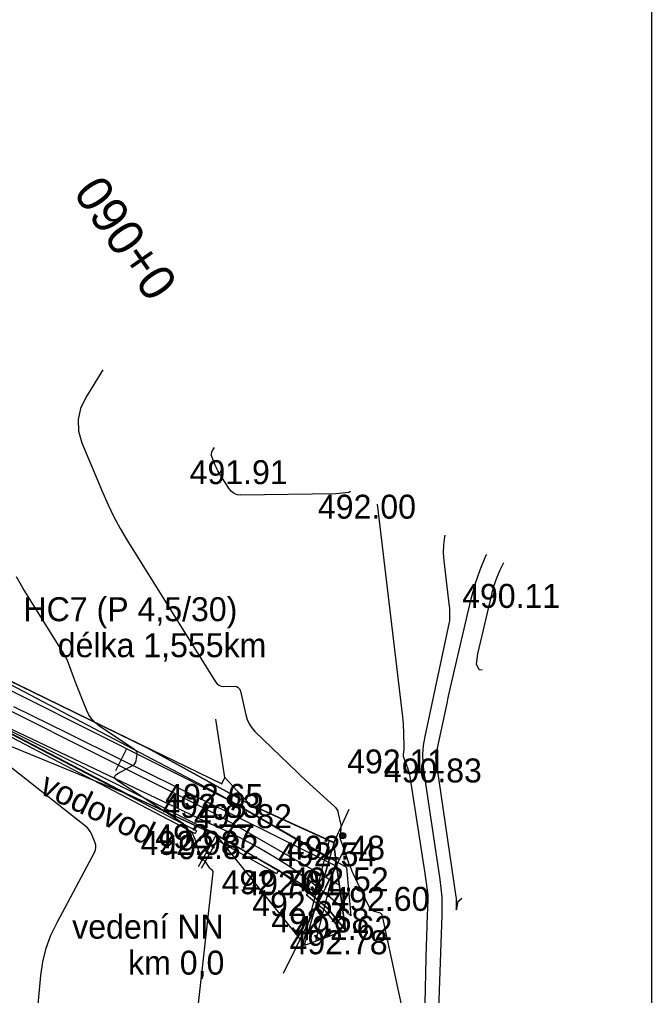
# Model space of a CAD drawing. Extents: x -636600 to -628587, y -1090963 to -1085869.
# Drawn here: x -629060 to -629007.3, y -1089333.5 to -1089252.1 of the extents above; entities that cross this region are included whole.
import ezdxf

# ---------------------------------------------------------------- set-up
doc = ezdxf.new("R2010")
doc.units = 0
for name, color, linetype in [('01_OBVOD PÚ', 7, 'Continuous'), ('01_PARCELY_NÁVRH_PC', 7, 'Continuous'), ('07_ELEKTRO', 7, 'Continuous'), ('07_OCH_P A POPISY TI', 7, 'Continuous'), ('07_VODOVOD', 7, 'Continuous'), ('08_LEGENDA_HV', 7, 'Continuous'), ('20', 7, 'Continuous'), ('23', 7, 'Continuous'), ('40', 7, 'Continuous'), ('52', 7, 'Continuous'), ('Ex_Major Contours', 7, 'Continuous'), ('Ex_Minor Contours', 7, 'Continuous'), ('HEKTOMETRY100', 7, 'Continuous'), ('HEKTOMETRY20', 7, 'Continuous'), ('HL_BODY', 7, 'Continuous'), ('koty_vše', 7, 'Continuous'), ('POLOMERY', 7, 'Continuous'), ('popis', 7, 'Continuous'), ('situace_osa', 7, 'Continuous'), ('situace_těleso', 7, 'Continuous'), ('situace_vozovka', 7, 'Continuous')]:
    doc.layers.add(name, color=color, linetype=linetype)

msp = doc.modelspace()

# ---------------------------------------------------------------- linework, layer by layer
at = {"layer": '01_OBVOD PÚ'}
msp.add_lwpolyline([(-629124.585, -1089274.487), (-629094.585, -1089282.287), (-629088.655, -1089283.337), (-629081.325, -1089299.317), (-629065.815, -1089310.587), (-629050.975, -1089316.657), (-629043.565, -1089320.077), (-629036.175, -1089329.257), (-629032.795, -1089328.017), (-629033.785, -1089320.707), (-629036.745, -1089319.347), (-629040.785, -1089317.497), (-629049.325, -1089312.807), (-629068.755, -1089303.327), (-629078.055, -1089290.717), (-629082.265, -1089284.067), (-629084.875, -1089279.947), (-629123.615, -1089269.707)], dxfattribs=at)
at = {"layer": '01_PARCELY_NÁVRH_PC'}
msp.add_lwpolyline([(-629124.585, -1089274.487), (-629123.615, -1089269.707), (-629084.875, -1089279.947), (-629078.055, -1089290.717), (-629068.755, -1089303.327), (-629049.325, -1089312.807), (-629040.785, -1089317.497), (-629036.745, -1089319.347), (-629033.785, -1089320.707), (-629032.795, -1089328.017), (-629034.275, -1089326.197), (-629035.865, -1089324.837), (-629038.385, -1089323.007), (-629043.565, -1089320.077), (-629050.975, -1089316.657), (-629073.783, -1089304.798), (-629074.736, -1089304.106), (-629074.865, -1089302.587), (-629088.655, -1089283.337), (-629094.585, -1089282.287)], close=True, dxfattribs=at)
at = {"layer": '07_ELEKTRO'}
msp.add_lwpolyline([(-629035.273, -1089328.926), (-629033.573, -1089322.277)], dxfattribs=at)
at = {"layer": '07_OCH_P A POPISY TI'}
msp.add_line((-629034.127, -1089322.051), (-629034.987, -1089325.019), dxfattribs=at)
for points in [[(-629034.127, -1089322.051), (-629042.702, -1089317.087), (-629070.938, -1089302.913), (-629075.743, -1089303.371)], [(-629034.987, -1089325.019), (-629044.128, -1089319.728), (-629071.513, -1089305.982), (-629072.074, -1089306.035)], [(-629034.15, -1089320.498), (-629036.363, -1089329.152)], [(-629034.15, -1089320.498), (-629033.725, -1089320.667), (-629036.225, -1089329.287), (-629036.363, -1089329.152)]]:
    msp.add_lwpolyline(points, dxfattribs=at)
at = {"layer": '07_VODOVOD'}
msp.add_lwpolyline([(-629073.913, -1089304.703), (-629071.225, -1089304.447), (-629043.415, -1089318.407), (-629033.304, -1089324.26)], dxfattribs=at)
at = {"layer": '08_LEGENDA_HV'}
msp.add_line((-629007.268, -1089189.968), (-629007.268, -1089486.968), dxfattribs=at)
at = {"layer": '20'}
for p, q in [((-629068.755, -1089303.337), (-629043.115, -1089315.807)), ((-629042.853, -1089315.268), (-629043.61, -1089310.397)), ((-629043.115, -1089315.807), (-629042.853, -1089315.268))]:
    msp.add_line(p, q, dxfattribs=at)
at = {"layer": '23'}
for p, q in [((-629069.245, -1089307.157), (-629045.225, -1089319.727)), ((-629069.357, -1089307.37), (-629045.337, -1089319.94)), ((-629040.785, -1089317.497), (-629042.853, -1089315.268)), ((-629033.755, -1089320.687), (-629040.785, -1089317.497)), ((-629032.516, -1089317.955), (-629033.755, -1089320.687)), ((-629045.225, -1089319.727), (-629045.337, -1089319.94)), ((-629045.05, -1089322.69), (-629043.575, -1089320.077)), ((-629043.575, -1089320.077), (-629038.385, -1089323.007)), ((-629044.789, -1089322.837), (-629043.462, -1089320.486)), ((-629043.462, -1089320.486), (-629038.533, -1089323.269)), ((-629038.385, -1089323.007), (-629038.533, -1089323.269)), ((-629035.865, -1089324.837), (-629036.06, -1089325.065)), ((-629034.491, -1089326.407), (-629036.06, -1089325.065)), ((-629034.275, -1089326.197), (-629035.865, -1089324.837)), ((-629034.491, -1089326.407), (-629033.039, -1089328.206)), ((-629034.275, -1089326.197), (-629032.805, -1089328.017))]:
    msp.add_line(p, q, dxfattribs=at)
at = {"layer": '40'}
for p, q in [((-629043.415, -1089316.637), (-629068.755, -1089303.337)), ((-629069.245, -1089307.157), (-629044.005, -1089319.177)), ((-629032.715, -1089322.777), (-629043.415, -1089316.637)), ((-629032.715, -1089322.777), (-629032.355, -1089326.817))]:
    msp.add_line(p, q, dxfattribs=at)
msp.add_arc((-629059.178, -1089355.015), 38.917, 46.43242, 67.05434, dxfattribs=at)
at = {"layer": '52'}
for radius in [0.25, 0.158, 0.05]:
    msp.add_circle((-629033.025, -1089320.127), radius, dxfattribs=at)
at = {"layer": 'Ex_Major Contours'}
msp.add_lwpolyline([(-629053.039, -1089281.281), (-629054.46, -1089283.571), (-629054.902, -1089284.49), (-629055.101, -1089285.428), (-629055.057, -1089286.386), (-629054.769, -1089287.364), (-629053.044, -1089291.522), (-629052.6, -1089292.534), (-629052.115, -1089293.525), (-629051.59, -1089294.495), (-629051.025, -1089295.445), (-629043.629, -1089307.306), (-629043.501, -1089307.468), (-629043.347, -1089307.582), (-629043.167, -1089307.65), (-629042.961, -1089307.67), (-629042.087, -1089307.657), (-629041.89, -1089307.681), (-629041.736, -1089307.759), (-629041.624, -1089307.891), (-629041.555, -1089308.077), (-629041.114, -1089310.055), (-629040.999, -1089310.442), (-629040.832, -1089310.799), (-629040.614, -1089311.128), (-629040.345, -1089311.428), (-629036.813, -1089314.842), (-629036.486, -1089315.155), (-629036.156, -1089315.466), (-629035.824, -1089315.774), (-629035.489, -1089316.08), (-629033.746, -1089317.654), (-629033.62, -1089317.785), (-629033.519, -1089317.931), (-629033.442, -1089318.091), (-629033.39, -1089318.265), (-629033.201, -1089319.114), (-629033.18, -1089319.233), (-629033.169, -1089319.352), (-629033.169, -1089319.472), (-629033.179, -1089319.592), (-629033.239, -1089320.073), (-629033.247, -1089320.193), (-629033.241, -1089320.311), (-629033.222, -1089320.428), (-629033.188, -1089320.543), (-629032.97, -1089321.168), (-629032.92, -1089321.31), (-629032.869, -1089321.452), (-629032.818, -1089321.594), (-629032.767, -1089321.736), (-629032.471, -1089322.543), (-629032.403, -1089322.724), (-629032.33, -1089322.903), (-629032.253, -1089323.08), (-629032.171, -1089323.256), (-629030.811, -1089326.095), (-629030.75, -1089326.196), (-629030.674, -1089326.278), (-629030.581, -1089326.341), (-629030.473, -1089326.386), (-629030.006, -1089326.527), (-629029.901, -1089326.573), (-629029.818, -1089326.64), (-629029.759, -1089326.727), (-629029.722, -1089326.836), (-629027.636, -1089336.542)], dxfattribs=at)
at = {"layer": 'Ex_Minor Contours'}
for points in [[(-629032.382, -1089291.426), (-629032.512, -1089291.508), (-629033.602, -1089291.61), (-629041.512, -1089291.728), (-629041.816, -1089291.698), (-629042.082, -1089291.598), (-629042.31, -1089291.428), (-629042.5, -1089291.189), (-629043.344, -1089289.836), (-629043.431, -1089289.689), (-629043.513, -1089289.538), (-629043.588, -1089289.384), (-629043.657, -1089289.227), (-629043.925, -1089288.581), (-629043.97, -1089288.429), (-629043.977, -1089288.28), (-629043.946, -1089288.134), (-629043.877, -1089287.991), (-629043.729, -1089287.753)], [(-629026.317, -1089341.491), (-629026.021, -1089329.133), (-629026.01, -1089328.724), (-629025.999, -1089328.316), (-629025.986, -1089327.908), (-629025.971, -1089327.499), (-629025.896, -1089325.447), (-629025.893, -1089325.248), (-629025.9, -1089325.05), (-629025.915, -1089324.853), (-629025.94, -1089324.656), (-629026.056, -1089323.869), (-629026.085, -1089323.672), (-629026.115, -1089323.476), (-629026.144, -1089323.279), (-629026.175, -1089323.083), (-629027.363, -1089315.383), (-629027.399, -1089315.181), (-629027.445, -1089314.981), (-629027.499, -1089314.783), (-629027.563, -1089314.588), (-629027.943, -1089313.512), (-629027.956, -1089313.468), (-629027.962, -1089313.423), (-629027.963, -1089313.377), (-629027.958, -1089313.331), (-629027.924, -1089313.146), (-629027.917, -1089313.1), (-629027.912, -1089313.053), (-629027.909, -1089313.006), (-629027.909, -1089312.959), (-629027.933, -1089311.348), (-629027.941, -1089311.064), (-629027.956, -1089310.781), (-629027.979, -1089310.498), (-629028.009, -1089310.215), (-629030.132, -1089292.465)], [(-629024.495, -1089295.068), (-629024.529, -1089295.207), (-629024.62, -1089295.863), (-629024.642, -1089296.525), (-629024.596, -1089297.193), (-629024.14, -1089301.001), (-629024.129, -1089301.11), (-629024.12, -1089301.219), (-629024.114, -1089301.328), (-629024.111, -1089301.437), (-629024.105, -1089301.875), (-629024.106, -1089301.984), (-629024.114, -1089302.093), (-629024.127, -1089302.201), (-629024.147, -1089302.308), (-629026.184, -1089311.853), (-629026.308, -1089312.594), (-629026.363, -1089313.336), (-629026.35, -1089314.08), (-629026.269, -1089314.827), (-629025.806, -1089317.825), (-629025.692, -1089318.568), (-629025.58, -1089319.31), (-629025.468, -1089320.053), (-629025.358, -1089320.796), (-629024.919, -1089323.769), (-629024.826, -1089324.513), (-629024.768, -1089325.259), (-629024.744, -1089326.007), (-629024.754, -1089326.756), (-629025.099, -1089336.166)], [(-629023.084, -1089325.373), (-629023.299, -1089325.563), (-629023.31, -1089325.57), (-629023.321, -1089325.576), (-629023.334, -1089325.579), (-629023.347, -1089325.579), (-629023.401, -1089325.577), (-629023.413, -1089325.578), (-629023.423, -1089325.583), (-629023.429, -1089325.591), (-629023.432, -1089325.603), (-629023.521, -1089326.211), (-629023.534, -1089326.29), (-629023.542, -1089326.316), (-629023.546, -1089326.289), (-629023.544, -1089326.209), (-629023.525, -1089325.701), (-629023.524, -1089325.581), (-629023.528, -1089325.461), (-629023.537, -1089325.342), (-629023.552, -1089325.222), (-629024.983, -1089315.532), (-629025.012, -1089315.338), (-629025.041, -1089315.144), (-629025.07, -1089314.951), (-629025.1, -1089314.757), (-629025.22, -1089313.982), (-629025.241, -1089313.789), (-629025.244, -1089313.596), (-629025.23, -1089313.403), (-629025.198, -1089313.211), (-629024.346, -1089309.22), (-629024.188, -1089308.491), (-629024.028, -1089307.764), (-629023.863, -1089307.036), (-629023.695, -1089306.31), (-629022.303, -1089300.359), (-629021.974, -1089299.141), (-629021.564, -1089297.954), (-629021.073, -1089296.798), (-629021.012, -1089296.677)], [(-629021.397, -1089306.322), (-629021.649, -1089306.286), (-629021.852, -1089305.818), (-629021.755, -1089304.955), (-629020.596, -1089300.002), (-629020.407, -1089299.303), (-629020.172, -1089298.621), (-629019.89, -1089297.957), (-629019.576, -1089297.34)], [(-629045.048, -1089334.119), (-629043.837, -1089323.155), (-629043.837, -1089323.12), (-629043.845, -1089323.088), (-629043.861, -1089323.06), (-629043.884, -1089323.034), (-629043.995, -1089322.937), (-629044.022, -1089322.912), (-629044.047, -1089322.885), (-629044.071, -1089322.858), (-629044.093, -1089322.829), (-629044.446, -1089322.337), (-629044.463, -1089322.314), (-629044.482, -1089322.292), (-629044.501, -1089322.27), (-629044.52, -1089322.248), (-629044.609, -1089322.156), (-629044.625, -1089322.143), (-629044.643, -1089322.138), (-629044.66, -1089322.14), (-629044.679, -1089322.15), (-629044.754, -1089322.204), (-629044.771, -1089322.214), (-629044.785, -1089322.214), (-629044.796, -1089322.205), (-629044.804, -1089322.187), (-629045.217, -1089320.772), (-629045.244, -1089320.685), (-629045.273, -1089320.6), (-629045.304, -1089320.515), (-629045.337, -1089320.432), (-629045.498, -1089320.044), (-629045.524, -1089319.99), (-629045.556, -1089319.941), (-629045.595, -1089319.896), (-629045.639, -1089319.857), (-629045.923, -1089319.634), (-629045.926, -1089319.63), (-629045.935, -1089319.619), (-629045.936, -1089319.618), (-629046.138, -1089319.316), (-629046.174, -1089319.267), (-629046.214, -1089319.223), (-629046.259, -1089319.183), (-629046.308, -1089319.147), (-629051.816, -1089315.544), (-629051.995, -1089315.388), (-629052.051, -1089315.238), (-629051.984, -1089315.092), (-629051.793, -1089314.951), (-629050.501, -1089314.242), (-629050.4, -1089314.173), (-629050.324, -1089314.087), (-629050.272, -1089313.984), (-629050.244, -1089313.866), (-629050.179, -1089313.358), (-629050.178, -1089313.238), (-629050.207, -1089313.132), (-629050.268, -1089313.04), (-629050.359, -1089312.962), (-629053.301, -1089310.993), (-629053.654, -1089310.717), (-629053.953, -1089310.399), (-629054.2, -1089310.039), (-629054.393, -1089309.636), (-629055.221, -1089307.532), (-629055.308, -1089307.31), (-629055.394, -1089307.087), (-629055.478, -1089306.865), (-629055.562, -1089306.641), (-629055.893, -1089305.748), (-629055.981, -1089305.527), (-629056.08, -1089305.311), (-629056.19, -1089305.101), (-629056.31, -1089304.896), (-629059.665, -1089299.517), (-629060.245, -1089298.542)], [(-629058.706, -1089337.206), (-629058.191, -1089331.796), (-629058.024, -1089330.637), (-629057.745, -1089329.512), (-629057.355, -1089328.42), (-629056.854, -1089327.362), (-629053.71, -1089321.48), (-629053.634, -1089321.296), (-629053.603, -1089321.109), (-629053.616, -1089320.921), (-629053.673, -1089320.73), (-629053.99, -1089319.963), (-629054.08, -1089319.779), (-629054.191, -1089319.611), (-629054.323, -1089319.459), (-629054.475, -1089319.323), (-629069.058, -1089307.868)]]:
    msp.add_lwpolyline(points, dxfattribs=at)
at = {"layer": 'HEKTOMETRY100'}
msp.add_lwpolyline([(-629034.446, -1089324.454), (-629032.675, -1089320.868)], dxfattribs=at)
at = {"layer": 'HEKTOMETRY20'}
msp.add_lwpolyline([(-629051.935, -1089314.7), (-629051.049, -1089312.907)], dxfattribs=at)
at = {"layer": 'HL_BODY'}
msp.add_lwpolyline([(-629033.56, -1089322.661), (-629037.989, -1089331.627)], dxfattribs=at)
at = {"layer": 'POLOMERY'}
msp.add_lwpolyline([(-629033.56, -1089322.661), (-629037.989, -1089331.627)], dxfattribs=at)
at = {"layer": 'situace_osa'}
msp.add_lwpolyline([(-629033.56, -1089322.661), (-629038.043, -1089320.447), (-629042.526, -1089318.232), (-629047.009, -1089316.018), (-629051.492, -1089313.803), (-629055.975, -1089311.589), (-629060.458, -1089309.375)], dxfattribs=at)
at = {"layer": 'situace_těleso'}
msp.add_lwpolyline([(-629127.165, -1089273.627), (-629124.585, -1089274.487), (-629094.585, -1089282.287), (-629088.655, -1089283.337), (-629074.865, -1089302.587), (-629074.736, -1089304.106), (-629073.783, -1089304.798), (-629050.975, -1089316.657), (-629043.565, -1089320.077), (-629038.385, -1089323.007), (-629035.865, -1089324.837), (-629034.275, -1089326.197), (-629032.795, -1089328.017), (-629033.785, -1089320.707), (-629036.745, -1089319.347), (-629040.785, -1089317.497), (-629049.325, -1089312.807), (-629068.755, -1089303.327), (-629078.055, -1089290.717), (-629084.875, -1089279.947), (-629123.615, -1089269.707), (-629123.576, -1089269.496)], dxfattribs=at)
at = {"layer": 'situace_vozovka'}
for points in [[(-629033.785, -1089320.707), (-629036.745, -1089319.347), (-629040.785, -1089317.497), (-629049.325, -1089312.807), (-629068.755, -1089303.327), (-629078.055, -1089290.717), (-629084.875, -1089279.947), (-629123.615, -1089269.707), (-629125.347, -1089269.259)], [(-629126.206, -1089273.677), (-629091.697, -1089282.799), (-629088.655, -1089283.337), (-629074.865, -1089302.587), (-629074.736, -1089304.106), (-629073.783, -1089304.798), (-629050.975, -1089316.657), (-629043.565, -1089320.077), (-629038.385, -1089323.007), (-629035.865, -1089324.837), (-629034.275, -1089326.197), (-629032.795, -1089328.017)]]:
    msp.add_lwpolyline(points, dxfattribs=at)

# ---------------------------------------------------------------- texts
at = {"layer": 'HEKTOMETRY20'}
msp.add_text('0+060', height=3, rotation=124.84789, dxfattribs=at).set_placement((-629046.667, -1089274.045))
at = {"layer": 'koty_vše'}
for s, p in [('491.91', (-629045.793, -1089290.807)), ('492.00', (-629035.092, -1089293.687)), ('490.11', (-629023.062, -1089301.127)), ('492.11', (-629032.655, -1089314.937)), ('490.83', (-629029.595, -1089315.687)), ('492.65', (-629047.824, -1089317.807)), ('492.83', (-629048.068, -1089318.637)), ('492.82', (-629045.438, -1089319.497)), ('492.77', (-629048.658, -1089321.177)), ('492.98', (-629049.886, -1089321.727)), ('492.82', (-629048.228, -1089322.077)), ('492.48', (-629037.678, -1089322.127)), ('492.54', (-629038.408, -1089322.687)), ('492.70', (-629043.125, -1089325.007)), ('492.61', (-629041.397, -1089325.087)), ('492.52', (-629037.368, -1089324.777)), ('492.67', (-629040.574, -1089326.837)), ('492.60', (-629033.97, -1089326.397)), ('492.68', (-629038.984, -1089328.197)), ('492.62', (-629037.064, -1089328.817)), ('492.78', (-629037.458, -1089330.017))]:
    msp.add_text(s, height=2, dxfattribs=at).set_placement(p)
at = {"layer": 'popis'}
for s, p in [('HC7 (P 4,5/30)', (-629059.648, -1089302.238)), ('délka 1,555km', (-629056.791, -1089305.238)), ('vedení NN', (-629055.588, -1089328.716)), ('km 0,0', (-629050.921, -1089331.716))]:
    msp.add_text(s, height=2, dxfattribs=at).set_placement(p)
msp.add_text('vodovod', height=2, rotation=333.8466, dxfattribs=at).set_placement((-629058.437, -1089316.544))

doc.saveas('drawing.dxf')
